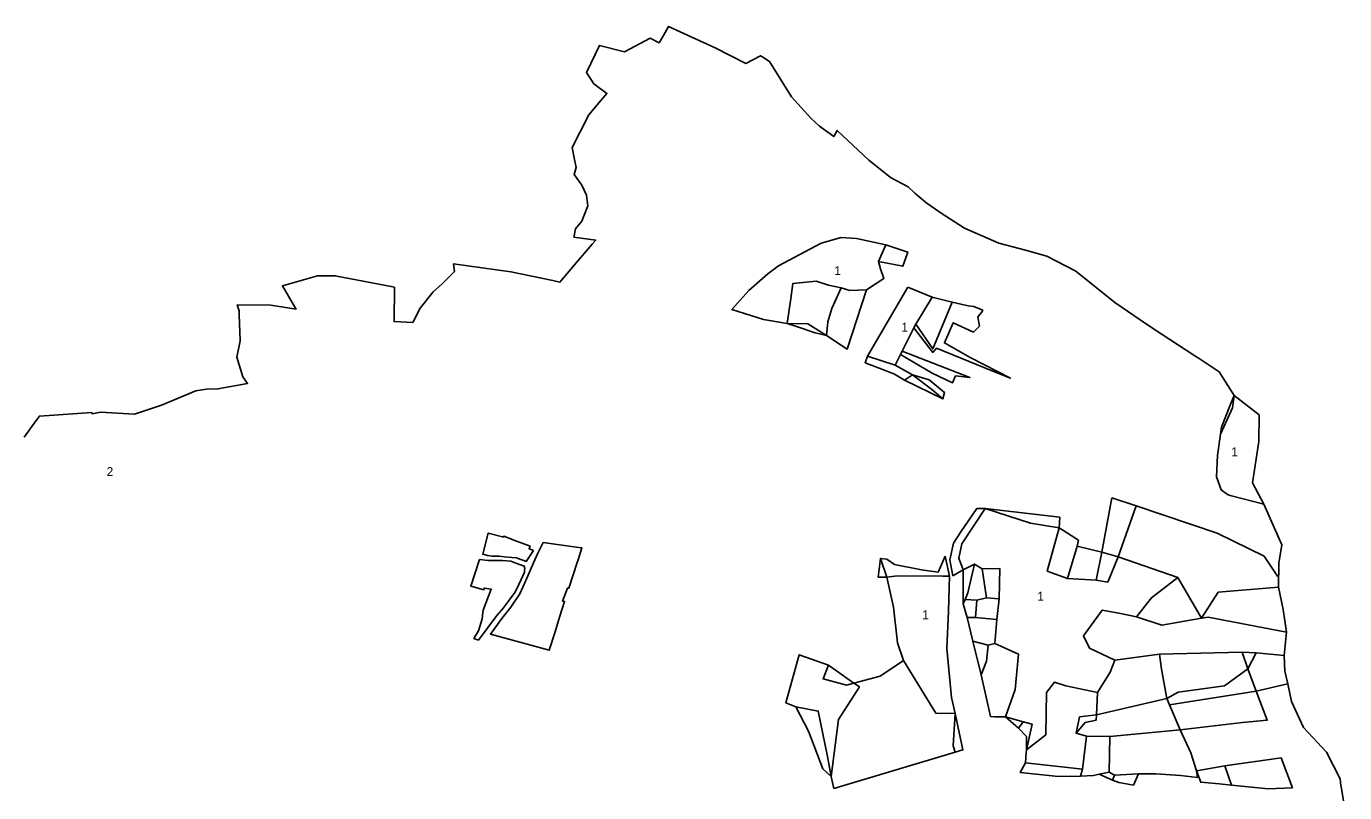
# Model space of a CAD drawing. Extents: x -790696 to -787271, y -1142331 to -1139378.
# Drawn here: x -789536 to -787693, y -1140449 to -1139378 of the extents above; entities that cross this region are included whole.
import ezdxf

# ---------------------------------------------------------------- set-up
doc = ezdxf.new("R2010")
doc.units = 0
for name, color, linetype in [('LES_ZV', 7, 'Continuous'), ('NERES_HRA', 7, 'Continuous'), ('NERES_SET', 7, 'Continuous'), ('OVNE_SET', 7, 'Continuous'), ('OVNI_SET', 7, 'Continuous'), ('OZN', 7, 'Continuous'), ('POR_SET', 7, 'Continuous')]:
    doc.layers.add(name, color=color, linetype=linetype)

msp = doc.modelspace()

# ---------------------------------------------------------------- linework, layer by layer
at = {"layer": 'LES_ZV'}
for points in [[(-788396.7, -1139673.1), (-788375.4, -1139674.5), (-788334.4, -1139683.2), (-788303.8, -1139693.4), (-788310.8, -1139713.2), (-788344.9, -1139706.7), (-788342, -1139716.9), (-788337.2, -1139730.5), (-788361.5, -1139746), (-788388.4, -1139829.1), (-788417.2, -1139810.2), (-788433.1, -1139806.3), (-788457.8, -1139797.7), (-788472.4, -1139793.4), (-788505.3, -1139787.6), (-788549.6, -1139773.7), (-788526.1, -1139747.3), (-788499.1, -1139723.6), (-788484.6, -1139712.6), (-788424.8, -1139680.8), (-788396.7, -1139673.1)], [(-788303.7, -1139742.3), (-788269.6, -1139756.6), (-788241.6, -1139763.6), (-788219.3, -1139768.4), (-788211.5, -1139769.6), (-788199, -1139774.6), (-788200.6, -1139777.8), (-788205.8, -1139783.7), (-788203.6, -1139797), (-788212, -1139805.2), (-788240.1, -1139792.2), (-788252.6, -1139820.5), (-788216.5, -1139840.8), (-788160.3, -1139869.7), (-788185, -1139859.7), (-788263.8, -1139827.9), (-788268.9, -1139833.6), (-788295.2, -1139799.4), (-788311.8, -1139831.8), (-788216.8, -1139868.7), (-788237, -1139866.3), (-788241.2, -1139876.1), (-788269.7, -1139862.8), (-788314.1, -1139836.7), (-788321.4, -1139851.4), (-788297, -1139864.9), (-788273.7, -1139872.1), (-788252.3, -1139889.8), (-788254.9, -1139898.8), (-788308.2, -1139872.6), (-788322.1, -1139863.9), (-788333.9, -1139859.3), (-788363.3, -1139848), (-788360.1, -1139838.7), (-788303.7, -1139742.3)], [(-787900.4, -1140418.8), (-787860.7, -1140411.9), (-787782, -1140400.6), (-787766.2, -1140442.6)], [(-787900.4, -1140418.8), (-787894.2, -1140434.7), (-787868.6, -1140437)], [(-787868.6, -1140437), (-787851.2, -1140438.6), (-787800.2, -1140443.7), (-787766.2, -1140442.6)]]:
    msp.add_lwpolyline(points, dxfattribs=at)
at = {"layer": 'NERES_HRA'}
for p, q in [((-788314.1, -1139836.7), (-788311.8, -1139831.8)), ((-787984.6, -1140048.2), (-788009.6, -1140119.6)), ((-788341.9, -1140121.6), (-788333, -1140147.9)), ((-787926.4, -1140148.6), (-788009.6, -1140119.6)), ((-788219.7, -1140169.9), (-788210.7, -1140129.7)), ((-788223.6, -1140179.1), (-788219.7, -1140169.9)), ((-788207.2, -1140179.9), (-788193.9, -1140176.7)), ((-788220.8, -1140204.1), (-788208.9, -1140204.4)), ((-787836.3, -1140252.9), (-787828.5, -1140276.3)), ((-787817, -1140253.5), (-787828.5, -1140276.3)), ((-788240.5, -1140383.9), (-788237.4, -1140338.6)), ((-788149.2, -1140359), (-788142.6, -1140350)), ((-788237.4, -1140392.6), (-788240.5, -1140383.9)), ((-788015, -1140424.9), (-788022.3, -1140420.5)), ((-788015, -1140424.9), (-788017.8, -1140431.8)), ((-787981.4, -1140423), (-788015, -1140424.9))]:
    msp.add_line(p, q, dxfattribs=at)
for points in [[(-787847.8, -1139893.7), (-787849.8, -1139911.2), (-787866.6, -1139948)], [(-788129.8, -1140353.6), (-788142.6, -1140350), (-788167.2, -1140343), (-788153.9, -1140305), (-788149, -1140255.6), (-788182.1, -1140240.7), (-788179.4, -1140207), (-788176.2, -1140178), (-788175.2, -1140135.6), (-788199.8, -1140136.4), (-788210.7, -1140129.7), (-788226.2, -1140137.8), (-788232.3, -1140121.2), (-788228.1, -1140101.3), (-788195.4, -1140051.8)], [(-788092.2, -1140078.8), (-788132.3, -1140072.5), (-788195.4, -1140051.8)], [(-788067.2, -1140104.6), (-788080.6, -1140149.6), (-788108.8, -1140139.5), (-788092.2, -1140078.8)], [(-788032.6, -1140112.9), (-788040.5, -1140151.9), (-788080.6, -1140149.6)], [(-788032.6, -1140112.9), (-788009.6, -1140119.6), (-788024.4, -1140154.9), (-788040.5, -1140151.9)], [(-788176.2, -1140178), (-788193.9, -1140176.7), (-788199.8, -1140136.4)], [(-788333, -1140147.9), (-788318.1, -1140145.9), (-788254.8, -1140146.3), (-788245.5, -1140146.5)], [(-787983.9, -1140203.2), (-787963.3, -1140176.6), (-787926.4, -1140148.6), (-787893.2, -1140205.4), (-787948.7, -1140215.1), (-787983.9, -1140203.2)], [(-787893.2, -1140205.4), (-787869.9, -1140168.9), (-787785.7, -1140161.7)], [(-788226.2, -1140185.1), (-788223.6, -1140179.1), (-788207.2, -1140179.9)], [(-788179.4, -1140207), (-788208.9, -1140204.4), (-788207.2, -1140179.9)], [(-788014.6, -1140263.8), (-788049.7, -1140247.3), (-788058.1, -1140230.1), (-788032.3, -1140194.2), (-788008.7, -1140198.1), (-787983.9, -1140203.2)], [(-787774.7, -1140225), (-787884.1, -1140203.9), (-787893.2, -1140205.4)], [(-788182.1, -1140240.7), (-788191.6, -1140242.9), (-788212.7, -1140237.2)], [(-788191.6, -1140242.9), (-788193.8, -1140265.3), (-788201.4, -1140284.5)], [(-788237.4, -1140338.6), (-788264.7, -1140337.9), (-788309.7, -1140264.4)], [(-788014.6, -1140263.8), (-788020.8, -1140280.9), (-788038.5, -1140309.4), (-788082.7, -1140299.9), (-788098.7, -1140294.7), (-788109.9, -1140309.4), (-788111, -1140368.2), (-788137.9, -1140389.2), (-788129.8, -1140353.6)], [(-787951.9, -1140255.5), (-787949, -1140276.6), (-787941.8, -1140317.6), (-788040.1, -1140340.2)], [(-787777.8, -1140257.3), (-787817, -1140253.5), (-787836.3, -1140252.9), (-787951.9, -1140255.5), (-788014.6, -1140263.8)], [(-788414.6, -1140271.1), (-788422.1, -1140290.2), (-788389.3, -1140298.9), (-788379.3, -1140296)], [(-787941.8, -1140317.6), (-787926.1, -1140308.7), (-787861, -1140299.9), (-787828.5, -1140276.3), (-787816.7, -1140307.1), (-787938.1, -1140326.2)], [(-788410.7, -1140426.8), (-788400.6, -1140346.9), (-788371.4, -1140301.2), (-788379.3, -1140296)], [(-788038.5, -1140309.4), (-788040.1, -1140340.2), (-788063.7, -1140343.4), (-788068.6, -1140366.1), (-788054.1, -1140370.4), (-788059.7, -1140416.3)], [(-787941.8, -1140317.6), (-787938.1, -1140326.2), (-787922.9, -1140361.4), (-788021.2, -1140370.6)], [(-788410.7, -1140426.8), (-788416.4, -1140396.3), (-788428.9, -1140335.2), (-788460, -1140329.4)], [(-788040.1, -1140340.2), (-788040.4, -1140347.7), (-788055.8, -1140351.3), (-788068.6, -1140366.1)], [(-788054.1, -1140370.4), (-788021.2, -1140370.6), (-788022.3, -1140420.5), (-788036.3, -1140423.5)], [(-788139.4, -1140407.4), (-788059.7, -1140416.3), (-788062.5, -1140426.3)]]:
    msp.add_lwpolyline(points, dxfattribs=at)
at = {"layer": 'NERES_SET'}
msp.add_line((-787981.4, -1140423), (-787988.1, -1140438.8), dxfattribs=at)
for points in [[(-787806.1, -1140045.9), (-787853.2, -1140033.8), (-787857.1, -1140032.5), (-787866, -1140025.8), (-787872.3, -1140007.6), (-787870.9, -1139977.9), (-787866.6, -1139948), (-787865.3, -1139938.4), (-787853.2, -1139907.2), (-787847.8, -1139893.7)], [(-787988.1, -1140438.8), (-788008.9, -1140435.2), (-788017.8, -1140431.8), (-788036.3, -1140423.5), (-788044, -1140425), (-788062.5, -1140426.3), (-788093.3, -1140426.6), (-788146.6, -1140420.9), (-788139.4, -1140407.4), (-788138.2, -1140393), (-788137.9, -1140389.2), (-788138, -1140370.6), (-788149.2, -1140359), (-788167.2, -1140343), (-788182.6, -1140343.4), (-788188.1, -1140342.7), (-788201.4, -1140284.5), (-788212.7, -1140237.2), (-788220.8, -1140204.1), (-788226.2, -1140185.1), (-788226.2, -1140137.8), (-788240.7, -1140146), (-788244.8, -1140123.9), (-788239.7, -1140100.4), (-788229.7, -1140084.4), (-788207.3, -1140052), (-788195.4, -1140051.8), (-788135.4, -1140059.1), (-788091.3, -1140064.2), (-788092.2, -1140078.8), (-788065.1, -1140096.2), (-788067.2, -1140104.6), (-788032.6, -1140112.9), (-788018.4, -1140037.2)], [(-788018.4, -1140037.2), (-787984.6, -1140048.2), (-787871.2, -1140086.2), (-787805.8, -1140118.6), (-787798.4, -1140129.7), (-787787.1, -1140146.6), (-787785.5, -1140148)], [(-788251.5, -1140118.4), (-788245.5, -1140146.5), (-788247, -1140195.6), (-788249.3, -1140247.7), (-788242.7, -1140316.4), (-788237.4, -1140338.6), (-788226.7, -1140389.4), (-788237.4, -1140392.6), (-788406.9, -1140443.4), (-788410.7, -1140426.8), (-788422.3, -1140415.9), (-788442.7, -1140363.1), (-788460, -1140329.4), (-788474.1, -1140323.6), (-788455.5, -1140256.3), (-788414.6, -1140271.1), (-788379.3, -1140296), (-788342.5, -1140286.2), (-788309.7, -1140264.4), (-788317.9, -1140239.8), (-788323.6, -1140189.8), (-788333, -1140147.9), (-788345.1, -1140147.8), (-788341.9, -1140121.6), (-788332.8, -1140122.6), (-788322.4, -1140130.4), (-788284.6, -1140137.5), (-788261.1, -1140140.8), (-788251.5, -1140118.4)], [(-787772.8, -1140297.2), (-787816.7, -1140307.1), (-787801.3, -1140348), (-787836.1, -1140351.3), (-787922.9, -1140361.4), (-787908.1, -1140393.6), (-787900.4, -1140418.8)], [(-787900.4, -1140418.8), (-787898.9, -1140428), (-787922.4, -1140425.3), (-787956.9, -1140423.1), (-787981.4, -1140423)]]:
    msp.add_lwpolyline(points, dxfattribs=at)
at = {"layer": 'OVNE_SET'}
msp.add_lwpolyline([(-789538.7, -1139952.3), (-789521.7, -1139928.8), (-789520, -1139926.5), (-789517.3, -1139922.7), (-789443.9, -1139917.7), (-789443.6, -1139919.4), (-789431.8, -1139917.2), (-789384.3, -1139920), (-789346.6, -1139907.2), (-789298.6, -1139887.3), (-789283.8, -1139885.2), (-789267.9, -1139884.6), (-789226.3, -1139877), (-789232.9, -1139868), (-789241.5, -1139840.1), (-789236.9, -1139817.6), (-789238.1, -1139780.5), (-789238.2, -1139775.4), (-789240.8, -1139767.3), (-789193.9, -1139767.5), (-789158.6, -1139773), (-789160.7, -1139769.3), (-789177.6, -1139740.7), (-789128.9, -1139726.6), (-789103.8, -1139726.4), (-789021.3, -1139742.6), (-789021.7, -1139790.5), (-788995.5, -1139791.7), (-788985.4, -1139771.8), (-788966.9, -1139748.9), (-788954.8, -1139738.4), (-788937.2, -1139720.5), (-788938.8, -1139710), (-788858.3, -1139720.8), (-788799.7, -1139733.3), (-788790, -1139735.4), (-788769.6, -1139711.4), (-788744.9, -1139682.4), (-788739.8, -1139676.5), (-788770.4, -1139672.3), (-788770.1, -1139670.8), (-788768.4, -1139663.1), (-788768, -1139661), (-788759.1, -1139650.2), (-788756, -1139641.8), (-788751.1, -1139628.9), (-788752.8, -1139613.8), (-788759.5, -1139599.7), (-788766.2, -1139589.9), (-788769.8, -1139584.7), (-788767.1, -1139575.1), (-788769.4, -1139563.9), (-788772.9, -1139547.1), (-788762.2, -1139526.3), (-788749.5, -1139501.6), (-788732.6, -1139481.4), (-788724.3, -1139471.6), (-788742.6, -1139458.2), (-788752.8, -1139442.2), (-788734.8, -1139404.4), (-788699.5, -1139413.2), (-788663.9, -1139394.5), (-788651.2, -1139400.8), (-788645.3, -1139390.4), (-788638, -1139377.8), (-788573, -1139407.8), (-788529.9, -1139429.5), (-788509.6, -1139418.8), (-788506.1, -1139420.8), (-788497.2, -1139426.8), (-788466.2, -1139476.2), (-788439.2, -1139506.1), (-788427, -1139517.5), (-788407.3, -1139531.9), (-788402.3, -1139523.2), (-788358, -1139564.8), (-788330.8, -1139586.9), (-788327.9, -1139589.3), (-788303.2, -1139602.1), (-788293.8, -1139611.2), (-788279, -1139623.6), (-788277.2, -1139625.2), (-788257.1, -1139638.9), (-788224.4, -1139659.9), (-788176.5, -1139680.7), (-788139.1, -1139690.7), (-788109.2, -1139699.1), (-788069.1, -1139720), (-788014.3, -1139764), (-787979.2, -1139788.2), (-787960.3, -1139800.6), (-787902.4, -1139838.4), (-787896.7, -1139842.1), (-787868.5, -1139860.6), (-787847.8, -1139893.7), (-787812.9, -1139921), (-787813, -1139958.2), (-787821.8, -1140016), (-787806.1, -1140045.9), (-787780.8, -1140102.5), (-787785.1, -1140128.2), (-787785.4, -1140142.5), (-787785.5, -1140148), (-787785.7, -1140161.7), (-787779.1, -1140192.9), (-787774.7, -1140225), (-787777.8, -1140257.3), (-787776.6, -1140279.5), (-787772.8, -1140297.2), (-787767.7, -1140321.9), (-787750.8, -1140358.3), (-787718.6, -1140392.8), (-787699.4, -1140429.7), (-787698.5, -1140439.3), (-787697.8, -1140443.2), (-787693.2, -1140469.6)], dxfattribs=at)
at = {"layer": 'OVNI_SET'}
for points in [[(-788826.8, -1140110.8), (-788837, -1140125.8), (-788838.8, -1140125.2), (-788845.7, -1140122.9), (-788850.5, -1140121), (-788857, -1140120.3), (-788867.8, -1140119.4), (-788874.9, -1140118.7), (-788875.4, -1140118.7), (-788884.4, -1140118.6), (-788890.4, -1140117.6), (-788891.3, -1140117.4), (-788897.8, -1140115.8), (-788890.4, -1140086.6), (-788870.1, -1140091.5), (-788868.8, -1140091.8), (-788868.5, -1140090.8), (-788850.6, -1140097.4), (-788849.3, -1140097.9), (-788831.7, -1140104.5), (-788833, -1140108.2), (-788826.8, -1140110.8)], [(-788813.2, -1140099.3), (-788767.1, -1140105.8), (-788759.1, -1140107.1), (-788764.2, -1140123.5), (-788765.6, -1140127.4), (-788777.6, -1140163.4), (-788779.1, -1140163.1), (-788786.3, -1140181.3), (-788783.4, -1140181.8), (-788790.3, -1140203.7), (-788796.6, -1140224.4), (-788805, -1140250.1), (-788886.9, -1140227.8), (-788870.9, -1140205.6), (-788858.7, -1140189.8), (-788845.8, -1140171.1), (-788837.7, -1140152.6), (-788826.6, -1140127.7), (-788820.7, -1140114.4), (-788813.2, -1140099.3)], [(-788903.8, -1140235.9), (-788910.2, -1140233.5), (-788903.7, -1140223), (-788898.7, -1140206.4), (-788897.8, -1140197.2), (-788897.3, -1140194), (-788885.8, -1140164.7), (-788895.1, -1140163.1), (-788895.3, -1140163), (-788896, -1140165.6), (-788914.4, -1140160.4), (-788902.2, -1140123.3), (-788890.4, -1140124.6), (-788877.1, -1140124.5), (-788870.2, -1140124.6), (-788858.3, -1140125.6), (-788851.5, -1140128.3), (-788845.2, -1140130.6), (-788839.8, -1140132.6), (-788839.1, -1140135.6), (-788839.3, -1140138.2), (-788839.5, -1140140.7), (-788844, -1140151.3), (-788847.3, -1140158.4), (-788849.3, -1140162.4), (-788853, -1140169.4), (-788860.7, -1140180.3), (-788867.9, -1140189.6), (-788868.5, -1140190.4), (-788878, -1140201.4), (-788903.8, -1140235.9)]]:
    msp.add_lwpolyline(points, dxfattribs=at)
at = {"layer": 'POR_SET'}
for p, q in [((-788344.9, -1139706.7), (-788334.4, -1139683.2)), ((-788292.5, -1139794.1), (-788269.6, -1139756.6)), ((-788417.2, -1139810.2), (-788415.4, -1139791)), ((-788321.4, -1139851.4), (-788360.1, -1139838.7)), ((-788308.2, -1139872.6), (-788297, -1139864.9)), ((-787860.7, -1140411.9), (-787851.2, -1140438.6))]:
    msp.add_line(p, q, dxfattribs=at)
for points in [[(-788472.4, -1139793.4), (-788467, -1139758.5), (-788464.2, -1139737.1), (-788431.6, -1139734), (-788414.7, -1139739.5), (-788396.7, -1139743.3)], [(-788415.4, -1139791), (-788410, -1139772.1), (-788396.7, -1139743.3), (-788384.8, -1139747), (-788361.5, -1139746)], [(-788295.2, -1139799.4), (-788292.5, -1139794.1), (-788268.8, -1139828.7), (-788241.6, -1139763.6)], [(-788472.4, -1139793.4), (-788443.2, -1139793.8), (-788417.2, -1139810.2)], [(-788297, -1139864.9), (-788270.5, -1139885.2), (-788254.9, -1139898.8)]]:
    msp.add_lwpolyline(points, dxfattribs=at)

# ---------------------------------------------------------------- texts
at = {"layer": 'OZN'}
for s, p in [('1', (-788406.4, -1139725.6)), ('1', (-788312.7, -1139804.5)), ('1', (-787851.6, -1139978.9)), ('2', (-789423.4, -1140006.6)), ('1', (-788122.8, -1140180.8)), ('1', (-788283.6, -1140206.8))]:
    msp.add_text(s, height=12.5, dxfattribs=at).set_placement(p)

doc.saveas('drawing.dxf')
